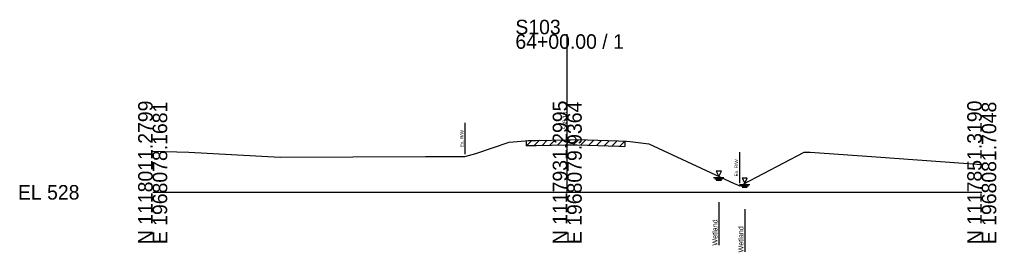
# Model space of a CAD drawing. Extents: x -26 to 163, y -10 to 24018.
# Drawn here: x -25.7 to 162.8, y 11988.4 to 12033.3 of the extents above; entities that cross this region are included whole.
import ezdxf

# ---------------------------------------------------------------- set-up
doc = ezdxf.new("R2010")
doc.units = 0
for name, color, linetype in [('RD_GPK_XS_Cell', 7, 'Continuous'), ('RD_XS_ExGround', 7, 'Continuous'), ('RD_XS_ExPaveRet', 7, 'Continuous'), ('RD_XS_ExRW', 7, 'Continuous'), ('RD_XS_EXWetland', 7, 'Continuous'), ('RD_XS_TX_Elev_EX', 7, 'Continuous')]:
    doc.layers.add(name, color=color, linetype=linetype)

msp = doc.modelspace()

# ---------------------------------------------------------------- linework, layer by layer
at = {"layer": 'RD_GPK_XS_Cell'}
for p, q in [((80, 12000), (80, 12030.48)), ((0, 12000), (80, 12000)), ((80, 12000), (160, 12000))]:
    msp.add_line(p, q, dxfattribs=at)
at = {"layer": 'RD_XS_ExGround'}
msp.add_lwpolyline([(0, 12007.94), (7.01, 12007.72), (24.6, 12006.78), (52.68, 12006.92), (60.25, 12006.88), (62.37, 12007.47), (68.81, 12009.65), (71.88, 12009.95), (72.48, 12010.02), (74.04, 12010.02), (80, 12010.13), (81.89, 12010.16), (89.91, 12009.91), (91.44, 12009.84), (92.15, 12009.77), (95.74, 12009.32), (112.19, 12001.73), (112.87, 12001.46), (113.22, 12001.24), (113.95, 12001.59), (125.7, 12007.77), (126.86, 12007.74), (139.64, 12006.87), (160, 12005.35)], dxfattribs=at)
at = {"layer": 'RD_XS_ExPaveRet'}
for p, q in [((72.15, 12008.98), (73.19, 12010.02)), ((72.15, 12008.98), (72.15, 12009.98)), ((73.65, 12009.02), (74.66, 12010.03)), ((75.15, 12009.04), (76.16, 12010.06)), ((76.65, 12009.07), (77.66, 12010.09)), ((78.15, 12009.09), (79.16, 12010.11)), ((79.65, 12009.12), (80.66, 12010.14)), ((81.15, 12009.15), (82.15, 12010.15)), ((82.65, 12009.14), (83.61, 12010.1)), ((84.15, 12009.09), (85.11, 12010.06)), ((85.65, 12009.04), (86.61, 12010.01)), ((87.15, 12008.99), (88.11, 12009.96)), ((88.65, 12008.95), (89.61, 12009.92)), ((90.15, 12008.9), (91.11, 12009.86)), ((91.13, 12009.85), (91.13, 12008.85)), ((72.15, 12008.98), (72.48, 12009.02)), ((72.48, 12009.02), (74.04, 12009.02)), ((74.04, 12009.02), (80, 12009.13)), ((80, 12009.13), (81.89, 12009.16)), ((81.89, 12009.16), (89.91, 12008.91)), ((89.91, 12008.91), (91.13, 12008.85))]:
    msp.add_line(p, q, dxfattribs=at)
at = {"layer": 'RD_XS_ExRW'}
for p, q in [((60.25, 12013.38), (60.25, 12007.38)), ((113.22, 12007.74), (113.22, 12001.74))]:
    msp.add_line(p, q, dxfattribs=at)
at = {"layer": 'RD_XS_EXWetland'}
for p, q in [((108.75, 12004.08), (109.25, 12003.08)), ((109.75, 12004.08), (108.75, 12004.08)), ((109.25, 12003.08), (109.75, 12004.08)), ((108.25, 12002.83), (110.25, 12002.83)), ((108.5, 12002.58), (110, 12002.58)), ((108.75, 12002.33), (109.75, 12002.33)), ((113.76, 12002.75), (114.26, 12001.75)), ((114.76, 12002.75), (113.76, 12002.75)), ((114.26, 12001.75), (114.76, 12002.75)), ((113.26, 12001.5), (115.26, 12001.5)), ((113.51, 12001.25), (115.01, 12001.25)), ((113.76, 12001), (114.76, 12001)), ((109.25, 11998.08), (109.25, 11989.83)), ((114.26, 11996.75), (114.26, 11988.5))]:
    msp.add_line(p, q, dxfattribs=at)

# ---------------------------------------------------------------- texts
at = {"layer": 'RD_GPK_XS_Cell'}
for s, p in [('S103', (70, 12030.48)), ('64+00.00 / 1', (70, 12027.68)), ('EL 528', (-26, 11998.6))]:
    msp.add_text(s, height=2.8, dxfattribs=at).set_placement(p)
for s, p in [('N 1118011.2799', (0, 11990)), ('E 1968078.1681', (2.8, 11990)), ('N 1117931.2995', (80, 11990)), ('E 1968079.9364', (82.8, 11990)), ('N 1117851.3190', (160, 11990)), ('E 1968081.7048', (162.8, 11990))]:
    msp.add_text(s, height=2.8, rotation=90, dxfattribs=at).set_placement(p)
at = {"layer": 'RD_XS_ExRW'}
for p in [(60, 12008.72), (112.97, 12003.08)]:
    msp.add_text('Ex. R/W ', height=0.65, rotation=90, dxfattribs=at).set_placement(p)
at = {"layer": 'RD_XS_EXWetland'}
for p in [(109, 11989.72), (114.01, 11988.4)]:
    msp.add_text('Wetland ', height=1, rotation=90, dxfattribs=at).set_placement(p)
at = {"layer": 'RD_XS_TX_Elev_EX'}
msp.add_text('538.13', height=0.8, rotation=90, dxfattribs=at).set_placement((79.9, 12012.13))

doc.saveas('drawing.dxf')
